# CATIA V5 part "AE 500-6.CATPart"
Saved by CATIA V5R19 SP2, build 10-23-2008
Part number: AE 500-6
Bounding box of the stored display mesh (mm): x -22.494 to 22.494, y -22.494 to 22.494, z 0 to 62
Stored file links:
  C:\Users\Bora\Desktop\3D Katı model\AE serisi\AE 500\AE 500-6.CATPart
  C:\Program Files\Dassault Systemes\B19\intel_a\reffiles\standard\MetricThickPitch.txt
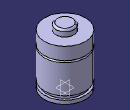
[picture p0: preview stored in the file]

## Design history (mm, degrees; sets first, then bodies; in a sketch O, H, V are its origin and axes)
Body1 (main body)
  Sketch1 on yz-plane, origin (0, 0, 0), H (0, 1, 0), V (0, 0, 1)
    point P1 (22.5, 39.5)
    point P8 (22.5, 41.5)
    point P9 (22.5, 41.5)
    point P10 (22.5, 39.5)
    point P11 (10, 60)
    point P13 (10, 60)
    line L1 (22.5, 39.5) -> (22.5, 8)
    line L2 (22.5, 4) -> (22.5, 0)
    line L3 (20, 8) -> (20, 4)
    line L4 (22.5, 55) -> (22.5, 41.5)
    arc A1 centre (22.5, 40.5) radius 1 from (22.5, 41.5) to (22.5, 39.5) ccw
    line L5 (10, 60) -> (10, 55)
    arc A2 centre (8, 60) radius 2 from (10, 60) to (8, 62) ccw
    line L6 (8, 62) -> (0, 62)
    point P15 (0, 62)
    line L7 (10, 55) -> (22.5, 55)
    line L8 (0, 0) -> (22.5, 0)
    line L9 (20, 8) -> (22.5, 8)
    line L10 (20, 4) -> (22.5, 4)
    coincidence: P15 V, P1 P10, P8 P9, P11 P13
    tangency: L6 A2
    horizontal: L7 H, L8 H, L9 H, L10 H
  Shaft1: profile Sketch1, axis Sketch1.V, angle 360
  Sketch2 on face of Shaft1 from Sketch1.L8, origin (0, 0, 0), H (1, 0, 0), V (0, -1, 0)
    point P1 (10, 0)
    distance P1 V = 10
  Hole1: placed by Sketch2, at (10, 0, 0) direction (0, 0, 1), diameter 6.647, depth 13, threaded "M8", thread diameter 8, thread depth 13, pitch 1.25
  CircPattern1: of Hole1, instances 2, angular step 180, axis from xy-plane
